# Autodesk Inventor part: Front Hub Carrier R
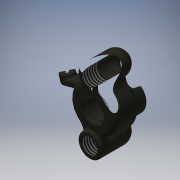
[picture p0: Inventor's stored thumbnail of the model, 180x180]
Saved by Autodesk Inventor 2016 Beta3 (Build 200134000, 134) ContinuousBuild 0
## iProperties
Shininess: 4.0
Length Units: 11272
Angle Units: 11279
Time Units: 11290
Mass Units: 11286
Length Display Precision: 3
Angle Display Precision: 2
Compacted: True
Company: Autodesk
Created: 2001-01
Part Number: Front Hub Carrier R
Document SubType Name: Modeling
Designer: Autodesk, Inc.
Project: Inventor Samples
User Status: IN PROGRESS
Density: 1.28 g/cm^3
Mass: 9.6969 g
Surface Area: 49.8526 cm^2
Volume: 7.5757 cm^3
Material: Stiffzel
Appearance: Stiffzel
Density: 0.0
Volumn: 0.0
Area: 0.0
PropertySet Name: Model Information
Control State: 0
Master: False
Checked Out: False
Last Check In Date: 2002-04-10
Last Check In By: Kevin.s
Author: Autodesk, Inc.
Revision Number: A
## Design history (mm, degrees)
derived "Front Hub Carrier L.ipt"
body "Solid1"
tag "TaggingFeature2"
feature "Solid1::Front Hub Carrier L.ipt" dims "d9" = 10
